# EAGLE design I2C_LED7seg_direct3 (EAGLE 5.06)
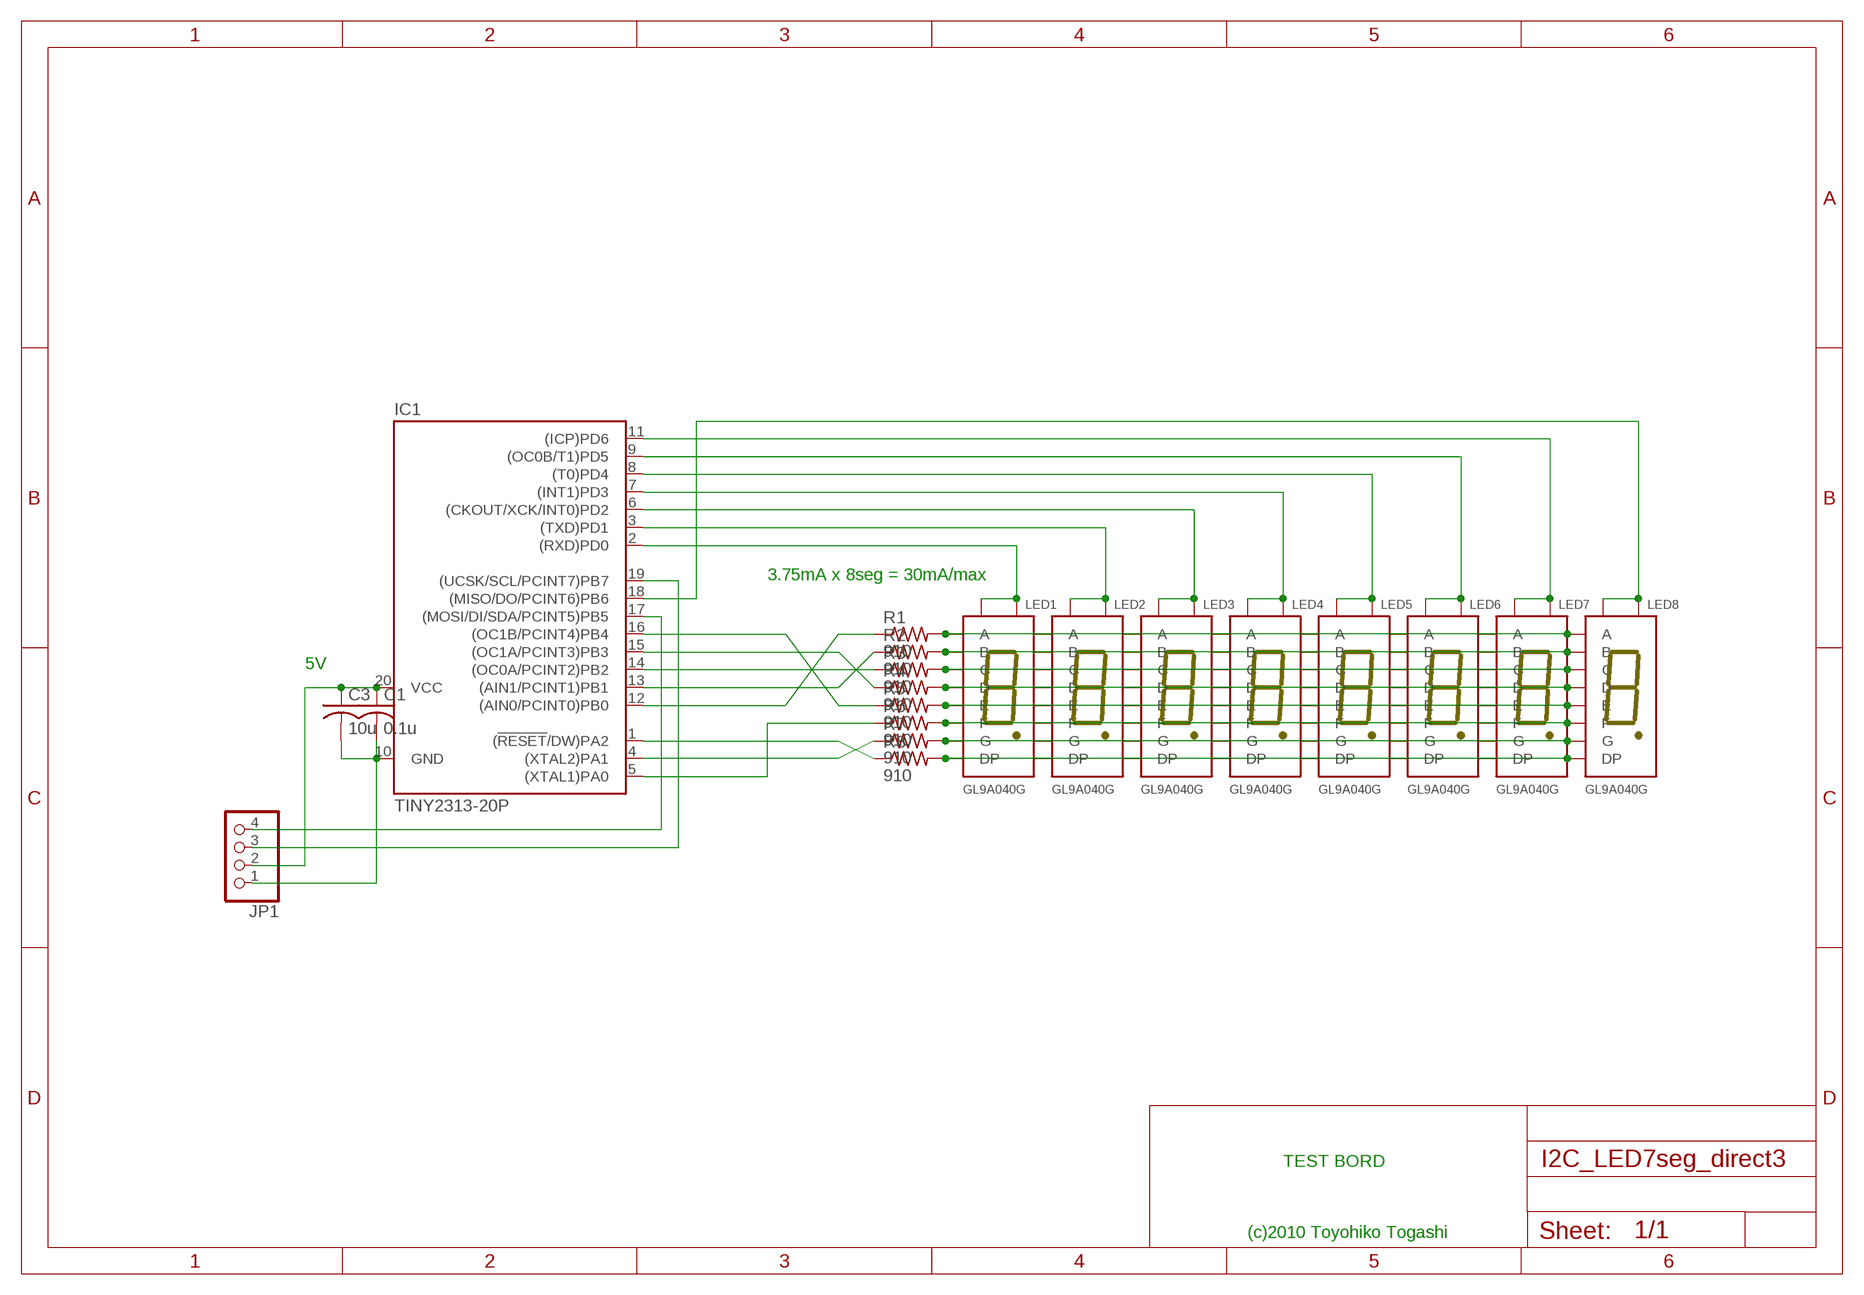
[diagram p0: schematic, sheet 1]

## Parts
C1  0.1u  C-US025-025X050  [C025-025X050]
C3  10u  C-US025-025X050  [C025-025X050]
IC1  TINY2313-20P  [DIL20]
JP1  PINHD-1X4  [1X04]
LED1  GL9A040G  [GL9A040G]
LED2  GL9A040G  [GL9A040G]
LED3  GL9A040G  [GL9A040G]
LED4  GL9A040G  [GL9A040G]
LED5  GL9A040G  [GL9A040G]
LED6  GL9A040G  [GL9A040G]
LED7  GL9A040G  [GL9A040G]
LED8  GL9A040G  [GL9A040G]
R1  910  R-US_0204/5  [0204/5]
R2  910  R-US_0204/5  [0204/5]
R3  910  R-US_0204/5  [0204/5]
R4  910  R-US_0204/5  [0204/5]
R5  910  R-US_0204/5  [0204/5]
R6  910  R-US_0204/7  [0204/7]
R7  910  R-US_0204/7  [0204/7]
R8  910  R-US_0204/7  [0204/7]

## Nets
N$1: C1.1 C3.1 IC1.20(VCC) JP1.2
N$2: LED1.P$10(A) LED2.P$10(A) LED3.P$10(A) LED4.P$10(A) LED5.P$10(A) LED6.P$10(A) LED7.P$10(A) LED8.P$10(A) R1.2
N$3: IC1.19((UCSK/SCL/PCINT7)PB7) JP1.3
N$4: IC1.17((MOSI/DI/SDA/PCINT5)PB5) JP1.4
N$6: LED1.P$9(B) LED2.P$9(B) LED3.P$9(B) LED4.P$9(B) LED5.P$9(B) LED6.P$9(B) LED7.P$9(B) LED8.P$9(B) R2.2
N$7: LED1.P$8(C) LED2.P$8(C) LED3.P$8(C) LED4.P$8(C) LED5.P$8(C) LED6.P$8(C) LED7.P$8(C) LED8.P$8(C) R3.2
N$8: LED1.P$5(D) LED2.P$5(D) LED3.P$5(D) LED4.P$5(D) LED5.P$5(D) LED6.P$5(D) LED7.P$5(D) LED8.P$5(D) R4.2
N$9: LED1.P$4(E) LED2.P$4(E) LED3.P$4(E) LED4.P$4(E) LED5.P$4(E) LED6.P$4(E) LED7.P$4(E) LED8.P$4(E) R5.2
N$10: LED1.P$2(F) LED2.P$2(F) LED3.P$2(F) LED4.P$2(F) LED5.P$2(F) LED6.P$2(F) LED7.P$2(F) LED8.P$2(F) R6.2
N$11: LED1.P$7(DP) LED2.P$7(DP) LED3.P$7(DP) LED4.P$7(DP) LED5.P$7(DP) LED6.P$7(DP) LED7.P$7(DP) LED8.P$7(DP) R8.2
N$12: LED1.P$3(G) LED2.P$3(G) LED3.P$3(G) LED4.P$3(G) LED5.P$3(G) LED6.P$3(G) LED7.P$3(G) LED8.P$3(G) R7.2
N$14: IC1.5((XTAL1)PA0) R6.1
N$15: IC1.4((XTAL2)PA1) R7.1
N$16: IC1.1((!RESET!/DW)PA2) R8.1
N$17: IC1.12((AIN0/PCINT0)PB0) R1.1
N$19: IC1.13((AIN1/PCINT1)PB1) R2.1
N$20: IC1.14((OC0A/PCINT2)PB2) R3.1
N$21: IC1.15((OC1A/PCINT3)PB3) R4.1
N$22: IC1.16((OC1B/PCINT4)PB4) R5.1
N$25: IC1.2((RXD)PD0) LED1.P$1(CA1) LED1.P$6(CA6)
N$28: IC1.18((MISO/DO/PCINT6)PB6) LED8.P$1(CA1) LED8.P$6(CA6)
N$33: C1.2 C3.2 IC1.10(GND) JP1.1
N$98: IC1.3((TXD)PD1) LED2.P$1(CA1) LED2.P$6(CA6)
N$99: IC1.6((CKOUT/XCK/INT0)PD2) LED3.P$1(CA1) LED3.P$6(CA6)
N$100: IC1.7((INT1)PD3) LED4.P$1(CA1) LED4.P$6(CA6)
N$101: IC1.8((T0)PD4) LED5.P$1(CA1) LED5.P$6(CA6)
N$102: IC1.9((OC0B/T1)PD5) LED6.P$1(CA1) LED6.P$6(CA6)
N$103: IC1.11((ICP)PD6) LED7.P$1(CA1) LED7.P$6(CA6)

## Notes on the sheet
- 3.75mA x 8seg = 30mA/max
- 5V
- TEST BORD
- (c)2010 Toyohiko Togashi

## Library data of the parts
C1 C3 = rcl:C-US: CAPACITOR, American symbol
IC1 = TOG:TINY2313: 8-bit AVR Microcontroller with 2K Bytes Flash Source: http://www.atmel.com .. doc2543.pdf
JP1 = pinhead:PINHD-1X4: PIN HEADER
LED1-LED8 = TOG:GL9A040G: 7 Segment LED
R1-R8 = rcl:R-US_: RESISTOR, American symbol

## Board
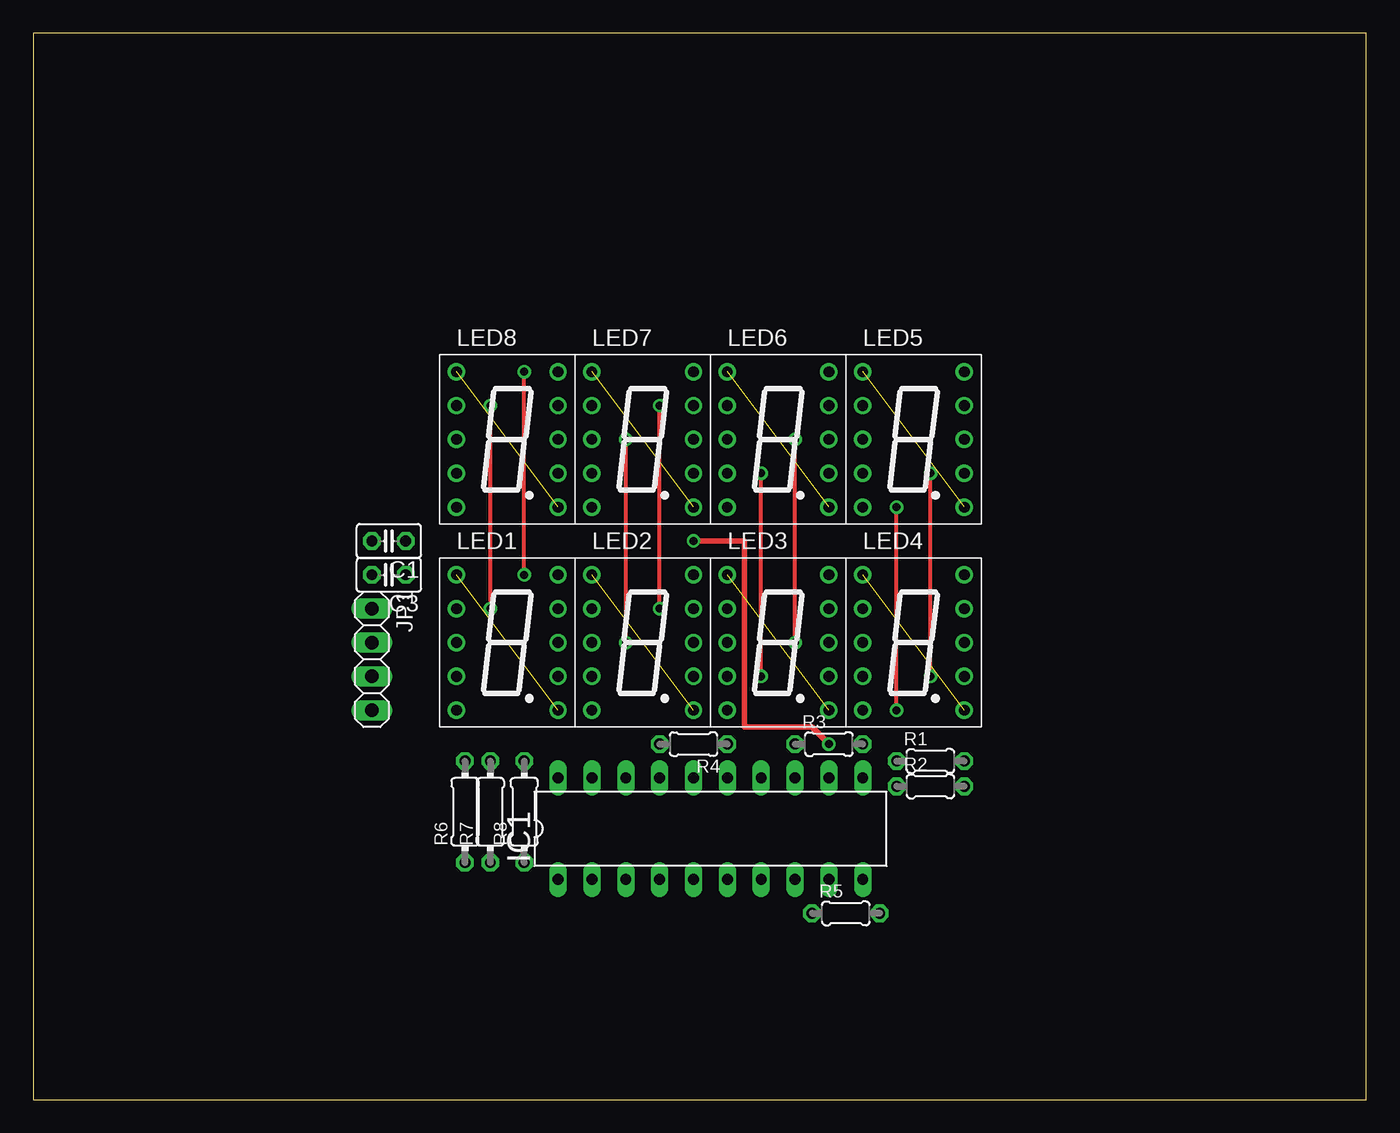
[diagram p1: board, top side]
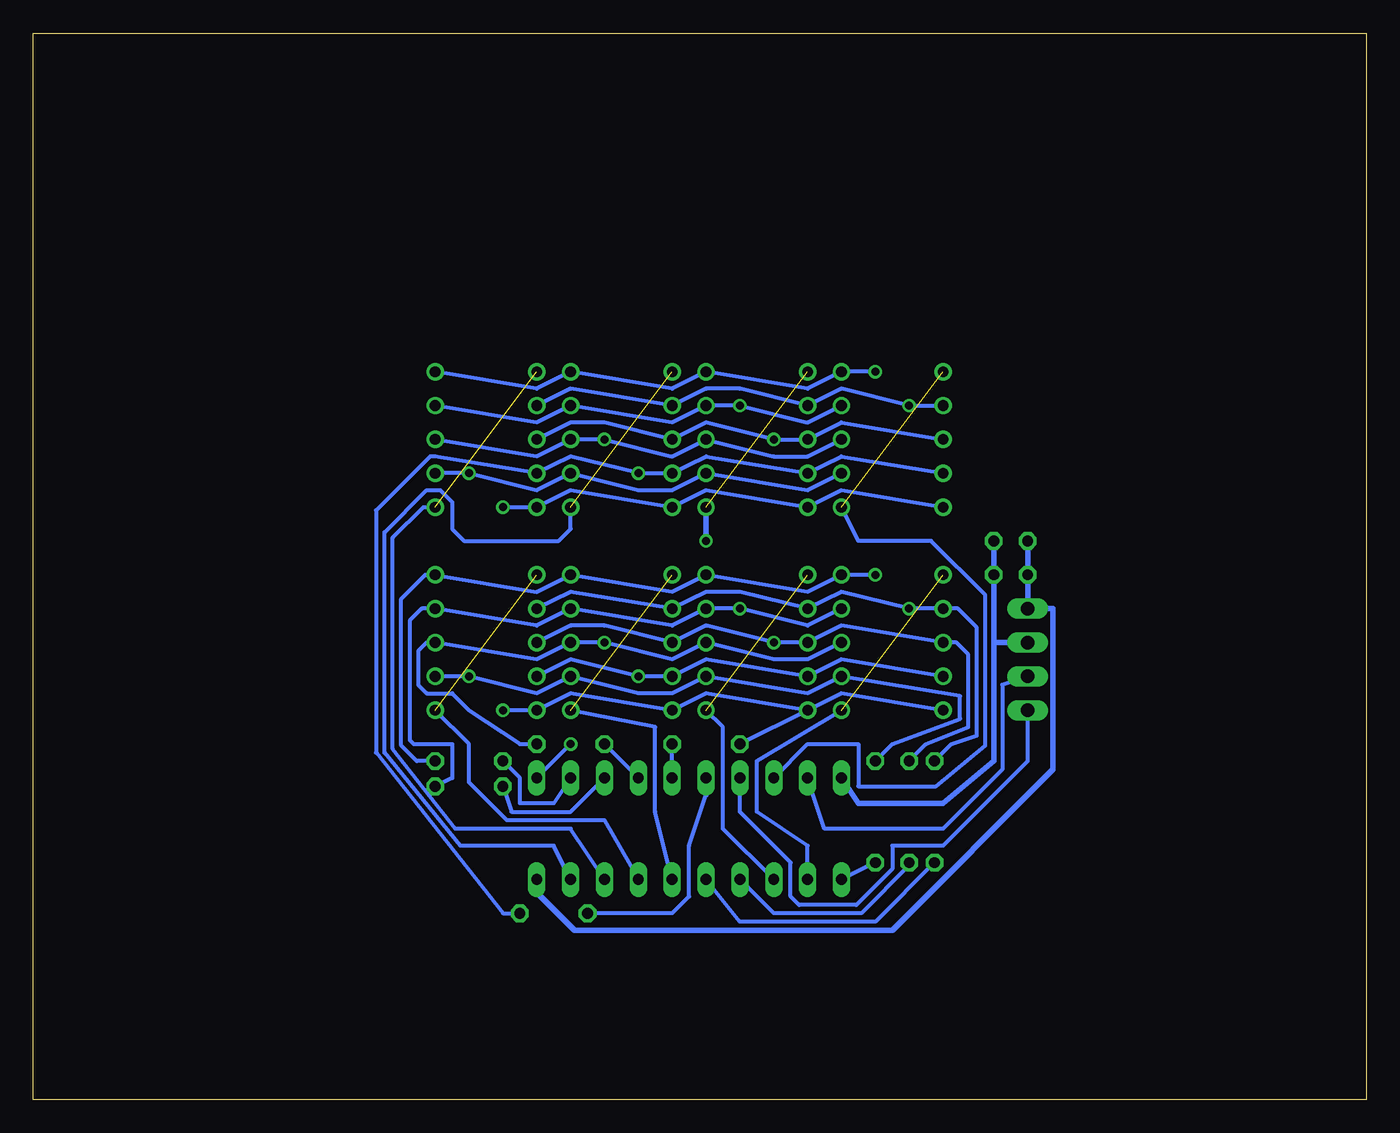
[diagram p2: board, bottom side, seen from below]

Size 100 x 80 mm. Coordinates in mm from the lower left corner, seen from the top.
Outline: 0,0 100,0 100,80 0,80 0,0
Copper layers (1*16): Top 0.035mm / dielectric 1.5mm / Bottom 0.035mm
Design rules "default": minimum track width 10mil, minimum drill 24mil, track to track 8mil, track to pad 8mil, pad to pad 8mil, via to via 8mil, smd to smd 8mil, copper to edge 40mil, drill to drill 8mil, minimum pad ring 10mil, minimum via ring 8mil, stop-mask expansion 4mil, vias tented up to drill 0mil, thermal gap 10mil

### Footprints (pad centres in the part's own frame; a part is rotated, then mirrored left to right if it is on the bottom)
C025-025X050 = drill 0.813 octagon: 1 -1.27,0; 2 1.27,0
DIL20 = drill 0.813 long: 1 -11.43,-3.81; 2 -8.89,-3.81; 3 -6.35,-3.81; 4 -3.81,-3.81; 5 -1.27,-3.81; 6 1.27,-3.81; 7 3.81,-3.81; 8 6.35,-3.81; 9 8.89,-3.81; 10 11.43,-3.81; 11 11.43,3.81; 12 8.89,3.81; 13 6.35,3.81; 14 3.81,3.81; 15 1.27,3.81; 16 -1.27,3.81; 17 -3.81,3.81; 18 -6.35,3.81; 19 -8.89,3.81; 20 -11.43,3.81
1X04 = drill 1.016 long: 1 -3.81,0; 2 -1.27,0; 3 1.27,0; 4 3.81,0
GL9A040G = drill 0.8 round: P$1 -3.81,5.08; P$2 -3.81,2.54; P$3 -3.81,0; P$4 -3.81,-2.54; P$5 -3.81,-5.08; P$6 3.81,-5.08; P$7 3.81,-2.54; P$8 3.81,0; P$9 3.81,2.54; P$10 3.81,5.08
0204/5 = drill 0.813 octagon: 1 -2.54,0; 2 2.54,0
0204/7 = drill 0.813 octagon: 1 -3.81,0; 2 3.81,0

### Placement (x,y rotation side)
C1  26.67,41.91 180 top
C3  26.67,39.37 180 top
IC1  50.8,20.32 0 top
JP1  25.4,33.02 270 top
LED1  35.56,34.29 0 top
LED2  45.72,34.29 0 top
LED3  55.88,34.29 0 top
LED4  66.04,34.29 0 top
LED5  66.04,49.53 0 top
LED6  55.88,49.53 0 top
LED7  45.72,49.53 0 top
LED8  35.56,49.53 0 top
R1  67.31,25.4 0 top
R2  67.31,23.5 0 top
R3  59.69,26.67 0 top
R4  49.53,26.67 180 top
R5  60.96,13.97 0 top
R6  32.38,21.59 90 top
R7  34.29,21.59 90 top
R8  36.83,21.59 90 top

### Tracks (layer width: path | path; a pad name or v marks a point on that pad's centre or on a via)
N$1
  Bottom 0.406: IC1.20 38.1,22.23 31.75,22.23 27.94,25.4 27.94,34.29 | 27.94,34.29 C3.1 C1.1 | 27.94,34.29 JP1.2
N$2  (via drill 0.6)
  Top 0.305: v36.83,39.37 v36.83,54.61
  Bottom 0.305: v36.83,54.61 LED8.P$10 41.91,53.34 LED7.P$10 52.07,53.34 LED6.P$10 62.23,53.34 LED5.P$10 | v36.83,39.37 LED1.P$10 41.91,38.1 LED2.P$10 52.07,38.1 LED3.P$10 62.23,38.1 LED4.P$10 70.59,39.37 72.39,37.57 72.39,26.56 71.23,25.4 R1.2
N$3
  Bottom 0.305: JP1.3 27.3,31.11 27.3,24.77 31.75,20.32 40.64,20.32 IC1.19
N$4
  Bottom 0.305: JP1.4 25.4,25.4 31.75,19.05 35.56,19.05 35.56,17.3 38.25,14.61 42.55,14.61 43.18,15.24 43.18,17.78 46.99,21.59 IC1.17
N$6  (via drill 0.6)
  Top 0.305: v46.99,36.83 v46.99,52.07
  Bottom 0.305: LED8.P$9 41.91,50.8 v46.99,52.07 LED7.P$9 52.07,50.8 LED6.P$9 62.23,50.8 LED5.P$9 | LED1.P$9 41.91,35.56 v46.99,36.83 LED2.P$9 52.07,35.56 LED3.P$9 62.23,35.56 LED4.P$9 70.86,36.83 71.75,35.93 71.75,26.97 71.45,26.67 68.58,26.67 68.58,24.13 R2.2
N$7  (via drill 0.6)
  Top 0.305: v57.15,34.29 v57.15,49.53
  Bottom 0.305: LED8.P$8 41.91,48.26 44.45,48.26 LED7.P$8 52.07,48.26 v57.15,49.53 LED6.P$8 62.23,48.26 LED5.P$8 | LED1.P$8 41.91,33.02 44.45,33.02 LED2.P$8 52.07,33.02 v57.15,34.29 LED3.P$8 62.23,33.02 LED4.P$8 70.48,34.29 71.12,33.66 71.12,31.11 70.48,30.48 68.58,30.48 67.31,29.21 63.5,26.67 R3.2
N$8  (via drill 0.6)
  Top 0.305: v64.77,29.21 v64.77,44.45
  Bottom 0.305: v64.77,29.21 LED4.P$5 59.69,30.48 LED3.P$5 49.53,30.48 LED2.P$5 | v64.77,44.45 LED5.P$5 59.69,45.72 LED6.P$5 49.53,45.72 LED7.P$5 39.37,45.72 LED8.P$5 | LED2.P$5 39.37,30.48 LED1.P$5 | LED2.P$5 R4.2
N$9  (via drill 0.6)
  Top 0.305: v54.61,31.75 v54.61,46.99
  Bottom 0.305: LED8.P$4 39.37,48.26 LED7.P$4 49.53,48.26 LED6.P$4 v54.61,46.99 59.69,48.26 LED5.P$4 69.85,48.26 70.23,48.26 74.3,44.19 74.3,26.04 64.77,13.97 R5.2 | LED1.P$4 39.37,33.02 LED2.P$4 49.53,33.02 LED3.P$4 v54.61,31.75 59.69,33.02 LED4.P$4
N$10  (via drill 0.6)
  Top 0.305: v34.29,36.83 v34.29,52.07
  Bottom 0.305: LED8.P$2 v34.29,52.07 39.37,53.34 LED7.P$2 46.99,53.34 49.53,53.34 LED6.P$2 59.69,53.34 LED5.P$2 | LED4.P$2 59.69,38.1 LED3.P$2 49.53,38.1 46.99,38.1 LED2.P$2 39.37,38.1 v34.29,36.83 LED1.P$2 30.63,36.83 29.21,35.41 29.21,27.3 31.11,26.67 R6.2
N$11  (via drill 0.6)
  Top 0.305: v67.31,31.75 v67.31,46.99
  Bottom 0.305: LED4.P$7 v67.31,31.75 62.23,30.48 LED3.P$7 54.61,30.48 52.07,30.48 LED2.P$7 41.91,30.48 LED1.P$7 30.48,30.27 30.48,28.57 35.56,26.67 R8.2 | LED5.P$7 v67.31,46.99 62.23,45.72 LED6.P$7 54.61,45.72 52.07,45.72 LED7.P$7 41.91,45.72 LED8.P$7
N$12  (via drill 0.6)
  Top 0.305: v44.45,34.29 v44.45,49.53
  Bottom 0.305: LED8.P$3 39.37,50.8 LED7.P$3 v44.45,49.53 49.53,50.8 LED6.P$3 57.15,50.8 59.69,50.8 LED5.P$3 | LED4.P$3 59.69,35.56 57.15,35.56 LED3.P$3 49.53,35.56 v44.45,34.29 LED2.P$3 39.37,35.56 LED1.P$3 30.74,34.29 29.84,33.39 29.84,27.94 33.02,26.67 R7.2
N$14
  Bottom 0.305: R6.1 36.83,13.34 46.99,13.34 IC1.5
N$15
  Bottom 0.305: R7.1 34.29,17.56 37.88,13.97 44.45,13.97 IC1.4
N$16
  Bottom 0.305: R8.1 IC1.1
N$17
  Bottom 0.305: IC1.12 60.96,22.23 63.5,22.23 63.5,24.13 R1.1
N$19
  Bottom 0.305: R2.1 64.14,21.59 59.69,21.59 IC1.13
N$20
  Bottom 0.305: IC1.14 R3.1
N$21
  Bottom 0.305: IC1.15 R4.1
N$22
  Bottom 0.305: 49.53,22.86 50.8,19.05 50.8,15.24 52.07,13.97 R5.1
  Bottom 0.406: 49.53,22.86 IC1.16
N$25  (1 unrouted)
  Bottom 0.305: IC1.2 41.91,19.05 45.72,21.59 45.72,25.4 LED1.P$6
N$28  (1 unrouted)
  Bottom 0.305: IC1.18 41.91,26.67 38.1,26.67 38.1,23.5 32.28,23.5 28.57,26.56 28.57,37.84 32.64,41.91 38.1,41.91 LED8.P$6
N$33
  Bottom 0.406: C1.2 C3.2 JP1.1 23.5,36.83 23.5,24.77 35.56,12.7 59.39,12.7 62.23,15.54 IC1.10
N$98  (1 unrouted)
  Bottom 0.305: IC1.3 48.26,20.32 48.26,27.94 LED2.P$6
N$99  (1 unrouted)
  Bottom 0.305: IC1.6 53.34,21.59 53.34,27.94 LED3.P$6
N$100  (1 unrouted)
  Bottom 0.305: IC1.7 57.15,20.95 64.47,20.95 67.31,23.8 67.31,26.67 LED4.P$6
N$101  (1 unrouted)
  Bottom 0.305: IC1.8 59.69,20.32 68.33,20.32 73.03,26.29 73.03,42.16 70.74,44.45 LED5.P$6
N$102  (1 unrouted)
  Bottom 0.305: IC1.9 60.96,19.05 67.94,19.05 73.66,26.04 73.66,42.55 70.48,45.72 69.48,45.72 68.58,44.82 68.58,42.81 67.68,41.91 60.59,41.91 59.69,42.81 LED6.P$6
N$103  (via drill 0.6)  (1 unrouted)
  Top 0.406: v49.53,41.91 53.34,41.91 53.34,27.94 58.42,27.94 v59.69,26.67
  Bottom 0.305: IC1.11 v59.69,26.67
  Bottom 0.406: v49.53,41.91 LED7.P$6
